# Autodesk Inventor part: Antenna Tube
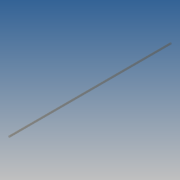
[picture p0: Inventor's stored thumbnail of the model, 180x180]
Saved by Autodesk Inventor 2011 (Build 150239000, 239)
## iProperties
Company: Autodesk Inc.
Created: 2010-06
Part Number: Antenna Tube
Document SubType Name: Modeling
Designer: Autodesk Inc.
Density: 1 g/cm^3
Catalog Web Link: http://www.vexrobotics.com/276-1196.html
Description: The Antenna Tube and holder help protect the Receiver's antenna and keep it away from metal. The cable connects the Receiver to
Vendor: Innovation First, Inc.
Author: Autodesk Inc.
Title: VEX Robotics Kit of Parts
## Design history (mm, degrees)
sketch "Sketch1"
  geometry: C1 r 1.473 at (0, 0); 1 further point
  constraints: 1 centre point, 1 coincident
  dimensions: "d0" = 2.9464 diameter of C1
extrude "Extrusion1" new body sketch "Sketch1" distance "d1" = 266.7; taper "d2" = 0 deg
sketch "Sketch2"
  geometry: C1 r 1.473 at (0, 0) reference
hole "Hole1" sketch "Sketch2" at (0, 0) diameter "d3" = 2.2352; stored, may be unused: countersink angle "d7" = 82 deg, drill point angle "d9" = 118 deg; dims "d4" = 19.05, "d5" = 9.525, "d6" = 6.35, "d8" = 25.4
body "Solid1"
